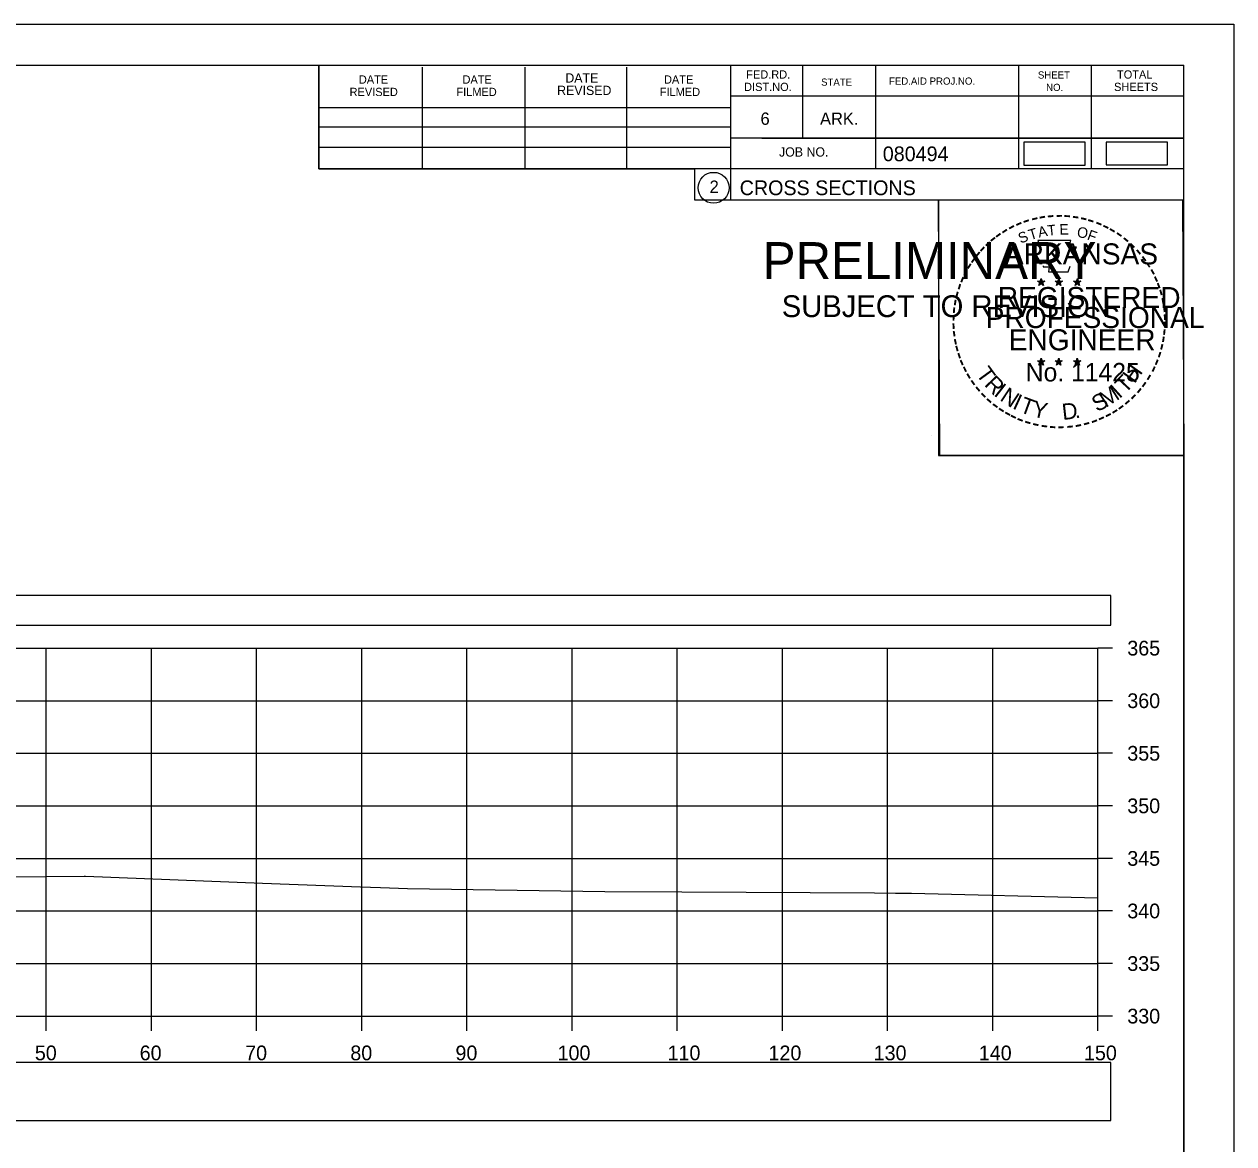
# Model space of a CAD drawing. Extents: x 1376273 to 1384221, y 378927 to 384592.
# Drawn here: x 1377105.7 to 1377220.7, y 380218.7 to 380325.2 of the extents above; entities that cross this region are included whole.
import ezdxf

# ---------------------------------------------------------------- set-up
doc = ezdxf.new("R2010")
doc.units = 0
for name, color, linetype in [('R_Axis', 7, 'Continuous'), ('R_Axis Annot', 7, 'Continuous'), ('R_Border', 7, 'Continuous'), ('R_Border PE', 7, 'Continuous'), ('R_Border Prem', 7, 'Continuous'), ('R_Drive', 7, 'Continuous'), ('R_Exist Surface', 7, 'Continuous'), ('R_Grid', 7, 'Continuous'), ('R_No Plot', 7, 'Continuous')]:
    doc.layers.add(name, color=color, linetype=linetype)

msp = doc.modelspace()

# ---------------------------------------------------------------- linework, layer by layer
at = {"layer": 'R_Axis'}
for p, q in [((1377207.77, 380230.82), (1377207.77, 380265.82)), ((1377209.17, 380265.82), (1377207.77, 380265.82)), ((1377209.17, 380260.82), (1377207.77, 380260.82)), ((1377209.17, 380255.82), (1377207.77, 380255.82)), ((1377209.17, 380250.82), (1377207.77, 380250.82)), ((1377209.17, 380245.82), (1377207.77, 380245.82)), ((1377209.17, 380240.82), (1377207.77, 380240.82)), ((1377209.17, 380235.82), (1377207.77, 380235.82)), ((1376907.77, 380230.82), (1377207.77, 380230.82)), ((1377107.77, 380229.42), (1377107.77, 380230.82)), ((1377117.77, 380229.42), (1377117.77, 380230.82)), ((1377127.77, 380229.42), (1377127.77, 380230.82)), ((1377137.77, 380229.42), (1377137.77, 380230.82)), ((1377147.77, 380229.42), (1377147.77, 380230.82)), ((1377157.77, 380229.42), (1377157.77, 380230.82)), ((1377167.77, 380229.42), (1377167.77, 380230.82)), ((1377177.77, 380229.42), (1377177.77, 380230.82)), ((1377187.77, 380229.42), (1377187.77, 380230.82)), ((1377197.77, 380229.42), (1377197.77, 380230.82)), ((1377207.77, 380229.42), (1377207.77, 380230.82)), ((1377209.17, 380230.82), (1377207.77, 380230.82))]:
    msp.add_line(p, q, dxfattribs=at)
at = {"layer": 'R_Axis Annot'}
for points in [[(1376907.2, 380268.02), (1377209.01, 380268.02), (1377209.01, 380270.84), (1376907.2, 380270.84)], [(1376907.2, 380220.89), (1377209.01, 380220.89), (1377209.01, 380226.41), (1376907.2, 380226.41)]]:
    msp.add_lwpolyline(points, close=True, dxfattribs=at)
at = {"layer": 'R_Border'}
for p, q in [((1376899.77, 380321.28), (1377215.95, 380321.28)), ((1377133.69, 380311.4), (1377133.69, 380321.28)), ((1377143.55, 380311.4), (1377143.55, 380321.08)), ((1377153.31, 380311.4), (1377153.31, 380321.08)), ((1377162.99, 380311.4), (1377162.99, 380321.08)), ((1377172.85, 380321.28), (1377172.85, 380308.48)), ((1377179.69, 380321.28), (1377179.69, 380314.34)), ((1377186.63, 380321.28), (1377186.63, 380311.4)), ((1377200.21, 380321.28), (1377200.21, 380311.4)), ((1377207.15, 380321.28), (1377207.15, 380311.4)), ((1377215.95, 380115.82), (1377215.95, 380321.28)), ((1377215.95, 380318.34), (1377172.85, 380318.34)), ((1377215.95, 380318.36), (1377215.95, 380318.36)), ((1377133.69, 380317.26), (1377172.85, 380317.26)), ((1377133.69, 380315.4), (1377172.85, 380315.4)), ((1377215.95, 380314.34), (1377172.85, 380314.34)), ((1377175.81, 380314.34), (1377215.95, 380314.34)), ((1377133.69, 380311.4), (1377133.69, 380313.46)), ((1377133.69, 380313.46), (1377172.85, 380313.46)), ((1377215.95, 380311.4), (1377133.69, 380311.4)), ((1377172.85, 380308.48), (1377215.95, 380308.48))]:
    msp.add_line(p, q, dxfattribs=at)
msp.add_circle((1377171.23, 380309.61), 1.47, dxfattribs=at)
at = {"layer": 'R_Border PE'}
for p, q in [((1377202.03, 380300.73), (1377202.38, 380300.62)), ((1377202.03, 380300.73), (1377202.29, 380300.69)), ((1377202.03, 380300.73), (1377202.27, 380300.61)), ((1377202.17, 380300.33), (1377202.38, 380300.62)), ((1377202.17, 380300.33), (1377202.29, 380300.57)), ((1377202.17, 380300.33), (1377202.38, 380300.54)), ((1377202.38, 380300.99), (1377202.34, 380300.74)), ((1377202.38, 380300.62), (1377202.38, 380300.99)), ((1377202.38, 380300.99), (1377202.43, 380300.74)), ((1377202.73, 380300.73), (1377202.38, 380300.62)), ((1377202.59, 380300.33), (1377202.38, 380300.62)), ((1377202.59, 380300.33), (1377202.38, 380300.54)), ((1377202.73, 380300.73), (1377202.44, 380300.68)), ((1377202.59, 380300.33), (1377202.46, 380300.62)), ((1377202.73, 380300.73), (1377202.52, 380300.63)), ((1377203.7, 380300.73), (1377204.05, 380300.62)), ((1377203.7, 380300.73), (1377203.96, 380300.69)), ((1377203.7, 380300.73), (1377203.94, 380300.61)), ((1377203.84, 380300.33), (1377204.05, 380300.62)), ((1377203.84, 380300.33), (1377203.96, 380300.57)), ((1377203.84, 380300.33), (1377204.05, 380300.54)), ((1377204.05, 380300.99), (1377204.01, 380300.74)), ((1377204.05, 380300.62), (1377204.05, 380300.99)), ((1377204.05, 380300.99), (1377204.1, 380300.74)), ((1377204.4, 380300.73), (1377204.05, 380300.62)), ((1377204.26, 380300.33), (1377204.05, 380300.62)), ((1377204.26, 380300.33), (1377204.05, 380300.54)), ((1377204.4, 380300.73), (1377204.11, 380300.68)), ((1377204.26, 380300.33), (1377204.13, 380300.62)), ((1377204.4, 380300.73), (1377204.19, 380300.63)), ((1377205.47, 380300.72), (1377205.82, 380300.61)), ((1377205.47, 380300.72), (1377205.72, 380300.68)), ((1377205.47, 380300.72), (1377205.7, 380300.6)), ((1377205.6, 380300.31), (1377205.82, 380300.61)), ((1377205.6, 380300.31), (1377205.73, 380300.56)), ((1377205.6, 380300.31), (1377205.81, 380300.53)), ((1377205.82, 380300.98), (1377205.77, 380300.72)), ((1377206.03, 380300.31), (1377205.81, 380300.53)), ((1377205.82, 380300.61), (1377205.82, 380300.98)), ((1377205.82, 380300.98), (1377205.86, 380300.73)), ((1377206.16, 380300.72), (1377205.82, 380300.61)), ((1377206.03, 380300.31), (1377205.82, 380300.61)), ((1377206.16, 380300.72), (1377205.88, 380300.67)), ((1377206.03, 380300.31), (1377205.89, 380300.6)), ((1377206.16, 380300.72), (1377205.96, 380300.62)), ((1377202.03, 380293.16), (1377202.38, 380293.05)), ((1377202.03, 380293.16), (1377202.28, 380293.12)), ((1377202.03, 380293.16), (1377202.27, 380293.04)), ((1377202.16, 380292.75), (1377202.38, 380293.05)), ((1377202.38, 380293.41), (1377202.34, 380293.16)), ((1377202.38, 380293.05), (1377202.38, 380293.41)), ((1377202.38, 380293.41), (1377202.43, 380293.16)), ((1377202.72, 380293.16), (1377202.38, 380293.05)), ((1377202.59, 380292.75), (1377202.38, 380293.05)), ((1377202.72, 380293.16), (1377202.44, 380293.11)), ((1377202.59, 380292.75), (1377202.45, 380293.04)), ((1377202.72, 380293.16), (1377202.52, 380293.06)), ((1377203.7, 380293.16), (1377204.05, 380293.05)), ((1377203.7, 380293.16), (1377203.95, 380293.12)), ((1377203.7, 380293.16), (1377203.93, 380293.04)), ((1377203.83, 380292.75), (1377204.05, 380293.05)), ((1377204.05, 380293.41), (1377204.01, 380293.16)), ((1377204.05, 380293.05), (1377204.05, 380293.41)), ((1377204.05, 380293.41), (1377204.1, 380293.16)), ((1377204.39, 380293.16), (1377204.05, 380293.05)), ((1377204.26, 380292.75), (1377204.05, 380293.05)), ((1377204.39, 380293.16), (1377204.11, 380293.11)), ((1377204.26, 380292.75), (1377204.12, 380293.04)), ((1377204.39, 380293.16), (1377204.19, 380293.06)), ((1377205.46, 380293.15), (1377205.81, 380293.04)), ((1377205.46, 380293.15), (1377205.72, 380293.11)), ((1377205.46, 380293.15), (1377205.7, 380293.03)), ((1377205.6, 380292.74), (1377205.81, 380293.04)), ((1377205.81, 380293.4), (1377205.77, 380293.15)), ((1377205.81, 380293.04), (1377205.81, 380293.4)), ((1377205.81, 380293.4), (1377205.86, 380293.15)), ((1377206.16, 380293.15), (1377205.81, 380293.04)), ((1377206.03, 380292.74), (1377205.81, 380293.04)), ((1377206.16, 380293.15), (1377205.87, 380293.1)), ((1377206.03, 380292.74), (1377205.89, 380293.03)), ((1377206.16, 380293.15), (1377205.96, 380293.05)), ((1377202.16, 380292.75), (1377202.29, 380293)), ((1377202.16, 380292.75), (1377202.38, 380292.97)), ((1377202.59, 380292.75), (1377202.38, 380292.97)), ((1377203.83, 380292.75), (1377203.96, 380293)), ((1377203.83, 380292.75), (1377204.04, 380292.97)), ((1377204.26, 380292.75), (1377204.04, 380292.97)), ((1377205.6, 380292.74), (1377205.72, 380292.99)), ((1377205.6, 380292.74), (1377205.81, 380292.96)), ((1377206.03, 380292.74), (1377205.81, 380292.96))]:
    msp.add_line(p, q, dxfattribs=at)
for points in [[(1377202.07, 380304.61), (1377202.34, 380303.78)], [(1377205.58, 380303.69), (1377205.73, 380303.97), (1377205.04, 380303.95), (1377205.19, 380304.61), (1377202.07, 380304.61)], [(1377202.57, 380302.19), (1377202.57, 380302.1), (1377203.13, 380302.08), (1377203.07, 380301.61), (1377204.94, 380301.61), (1377205.15, 380302.15)], [(1377202.38, 380300.99), (1377202.59, 380300.33), (1377202.03, 380300.73), (1377202.73, 380300.73), (1377202.17, 380300.33), (1377202.38, 380300.99)], [(1377204.05, 380300.99), (1377204.26, 380300.33), (1377203.7, 380300.73), (1377204.4, 380300.73), (1377203.84, 380300.33), (1377204.05, 380300.99)], [(1377205.82, 380300.98), (1377206.03, 380300.31), (1377205.47, 380300.72), (1377206.16, 380300.72), (1377205.6, 380300.31), (1377205.82, 380300.98)], [(1377202.38, 380293.41), (1377202.59, 380292.75), (1377202.03, 380293.16), (1377202.72, 380293.16), (1377202.16, 380292.75), (1377202.38, 380293.41)], [(1377204.05, 380293.41), (1377204.26, 380292.75), (1377203.7, 380293.16), (1377204.39, 380293.16), (1377203.83, 380292.75), (1377204.05, 380293.41)], [(1377205.81, 380293.4), (1377206.03, 380292.74), (1377205.46, 380293.15), (1377206.16, 380293.15), (1377205.6, 380292.74), (1377205.81, 380293.4)]]:
    msp.add_lwpolyline(points, dxfattribs=at)
for centre, radius in [((1377202.38, 380300.62), 0.172), ((1377202.38, 380300.62), 0.145), ((1377202.38, 380300.62), 0.116), ((1377202.38, 380300.62), 0.0991), ((1377202.38, 380300.62), 0.0747), ((1377202.38, 380300.62), 0.0495), ((1377202.38, 380300.62), 0.0296), ((1377204.05, 380300.62), 0.172), ((1377204.05, 380300.62), 0.145), ((1377204.05, 380300.62), 0.116), ((1377204.05, 380300.62), 0.0991), ((1377204.05, 380300.62), 0.0747), ((1377204.05, 380300.62), 0.0495), ((1377204.05, 380300.62), 0.0296), ((1377205.81, 380300.61), 0.172), ((1377205.81, 380300.61), 0.145), ((1377205.81, 380300.61), 0.116), ((1377205.81, 380300.61), 0.0991), ((1377205.81, 380300.61), 0.0747), ((1377205.81, 380300.61), 0.0495), ((1377205.81, 380300.61), 0.0296), ((1377202.38, 380293.05), 0.172), ((1377202.38, 380293.05), 0.145), ((1377202.38, 380293.05), 0.116), ((1377202.38, 380293.05), 0.0991), ((1377202.38, 380293.05), 0.0747), ((1377202.38, 380293.05), 0.0495), ((1377202.38, 380293.05), 0.0296), ((1377204.05, 380293.05), 0.172), ((1377204.05, 380293.05), 0.145), ((1377204.05, 380293.05), 0.116), ((1377204.05, 380293.05), 0.0991), ((1377204.05, 380293.05), 0.0747), ((1377204.05, 380293.05), 0.0495), ((1377204.05, 380293.05), 0.0296), ((1377205.81, 380293.04), 0.172), ((1377205.81, 380293.04), 0.145), ((1377205.81, 380293.04), 0.116), ((1377205.81, 380293.04), 0.0991), ((1377205.81, 380293.04), 0.0747), ((1377205.81, 380293.04), 0.0495), ((1377205.81, 380293.04), 0.0296)]:
    msp.add_circle(centre, radius, dxfattribs=at)
at = {"layer": 'R_Drive'}
for points in [[(1377200.72, 380311.77), (1377206.55, 380311.77), (1377206.55, 380313.96), (1377200.72, 380313.96)], [(1377208.55, 380311.78), (1377214.39, 380311.78), (1377214.39, 380313.96), (1377208.55, 380313.96)]]:
    msp.add_lwpolyline(points, close=True, dxfattribs=at)
at = {"layer": 'R_Exist Surface'}
msp.add_lwpolyline([(1377093.38, 380243.97), (1377111.36, 380244.14), (1377111.49, 380244.14), (1377128.33, 380243.45), (1377137.64, 380243.11), (1377139.54, 380243.04), (1377142.11, 380242.96), (1377160.87, 380242.67), (1377168.2, 380242.63), (1377186.53, 380242.54), (1377188.53, 380242.52), (1377190.06, 380242.52), (1377207.77, 380242.08)], dxfattribs=at)
at = {"layer": 'R_Grid'}
for p, q in [((1376907.77, 380265.82), (1377207.77, 380265.82)), ((1376907.77, 380265.82), (1377207.77, 380265.82)), ((1377107.77, 380230.82), (1377107.77, 380265.82)), ((1377107.77, 380230.82), (1377107.77, 380265.82)), ((1377117.77, 380230.82), (1377117.77, 380265.82)), ((1377117.77, 380230.82), (1377117.77, 380265.82)), ((1377127.77, 380230.82), (1377127.77, 380265.82)), ((1377127.77, 380230.82), (1377127.77, 380265.82)), ((1377137.77, 380230.82), (1377137.77, 380265.82)), ((1377137.77, 380230.82), (1377137.77, 380265.82)), ((1377147.77, 380230.82), (1377147.77, 380265.82)), ((1377147.77, 380230.82), (1377147.77, 380265.82)), ((1377157.77, 380230.82), (1377157.77, 380265.82)), ((1377157.77, 380230.82), (1377157.77, 380265.82)), ((1377167.77, 380230.82), (1377167.77, 380265.82)), ((1377167.77, 380230.82), (1377167.77, 380265.82)), ((1377177.77, 380230.82), (1377177.77, 380265.82)), ((1377177.77, 380230.82), (1377177.77, 380265.82)), ((1377187.77, 380230.82), (1377187.77, 380265.82)), ((1377187.77, 380230.82), (1377187.77, 380265.82)), ((1377197.77, 380230.82), (1377197.77, 380265.82)), ((1377197.77, 380230.82), (1377197.77, 380265.82)), ((1377207.77, 380230.82), (1377207.77, 380265.82)), ((1377207.77, 380230.82), (1377207.77, 380265.82)), ((1376907.77, 380260.82), (1377207.77, 380260.82)), ((1376907.77, 380260.82), (1377207.77, 380260.82)), ((1376907.77, 380255.82), (1377207.77, 380255.82)), ((1376907.77, 380255.82), (1377207.77, 380255.82)), ((1376907.77, 380250.82), (1377207.77, 380250.82)), ((1376907.77, 380250.82), (1377207.77, 380250.82)), ((1376907.77, 380245.82), (1377207.77, 380245.82)), ((1376907.77, 380245.82), (1377207.77, 380245.82)), ((1376907.77, 380240.82), (1377207.77, 380240.82)), ((1376907.77, 380240.82), (1377207.77, 380240.82)), ((1376907.77, 380235.82), (1377207.77, 380235.82)), ((1376907.77, 380235.82), (1377207.77, 380235.82)), ((1376907.77, 380230.82), (1377207.77, 380230.82)), ((1376907.77, 380230.82), (1377207.77, 380230.82))]:
    msp.add_line(p, q, dxfattribs=at)
at = {"layer": 'R_No Plot'}
for p, q in [((1376887.37, 380325.17), (1377220.7, 380325.17)), ((1377191.98, 380286.02), (1377191.98, 380286.02))]:
    msp.add_line(p, q, dxfattribs=at)
for points in [[(1376887.36, 380325.17), (1377220.7, 380325.17), (1377220.7, 380111.84), (1376887.36, 380111.84)], [(1377133.69, 380321.28), (1377133.69, 380311.4), (1377169.42, 380311.4), (1377169.42, 380308.48), (1377192.62, 380308.48), (1377192.62, 380284.15), (1377215.95, 380284.15), (1377215.95, 380115.82), (1376899.77, 380115.82), (1376899.77, 380321.28)], [(1377192.62, 380308.48), (1377215.83, 380308.48), (1377215.95, 380284.15), (1377192.74, 380284.15)]]:
    msp.add_lwpolyline(points, close=True, dxfattribs=at)

# ---------------------------------------------------------------- texts
at = {"layer": 'R_Axis Annot'}
for s, p in [('365', (1377210.57, 380265.12)), ('360', (1377210.57, 380260.12)), ('355', (1377210.57, 380255.12)), ('350', (1377210.57, 380250.12)), ('345', (1377210.57, 380245.12)), ('340', (1377210.57, 380240.12)), ('335', (1377210.57, 380235.12)), ('330', (1377210.57, 380230.12)), ('50', (1377106.68, 380226.62)), ('60', (1377116.65, 380226.62)), ('70', (1377126.68, 380226.62)), ('80', (1377136.68, 380226.62)), ('90', (1377146.68, 380226.62)), ('100', (1377156.39, 380226.62)), ('110', (1377166.85, 380226.62)), ('120', (1377176.45, 380226.62)), ('130', (1377186.45, 380226.62)), ('140', (1377196.45, 380226.62)), ('150', (1377206.45, 380226.62))]:
    msp.add_text(s, height=1.4, dxfattribs=at).set_placement(p)
at = {"layer": 'R_Border'}
for s, height, p in [('FED.RD.', 0.782, (1377174.33, 380320)), ('SHEET', 0.684, (1377202.07, 380320)), ('TOTAL', 0.782, (1377209.59, 380320)), ('DATE', 0.782, (1377137.49, 380319.52)), ('DATE', 0.782, (1377147.35, 380319.52)), ('DATE', 0.879, (1377157.13, 380319.62)), ('DATE', 0.782, (1377166.51, 380319.52)), ('DIST.NO.', 0.782, (1377174.13, 380318.82)), ('STATE', 0.684, (1377181.45, 380319.32)), ('FED.AID PROJ.NO.', 0.684, (1377187.91, 380319.42)), ('NO.', 0.684, (1377202.85, 380318.82)), ('SHEETS', 0.782, (1377209.31, 380318.82)), ('REVISED', 0.782, (1377136.61, 380318.34)), ('FILMED', 0.782, (1377146.77, 380318.34)), ('REVISED', 0.879, (1377156.35, 380318.44)), ('FILMED', 0.782, (1377166.11, 380318.34)), ('6', 1.17, (1377175.69, 380315.6)), ('ARK.', 1.172, (1377181.35, 380315.6)), ('JOB NO.', 0.879, (1377177.45, 380312.58)), ('080494', 1.4, (1377187.32, 380312.14)), ('2', 1.17, (1377170.85, 380309.13)), ('CROSS SECTIONS', 1.4, (1377173.71, 380308.91))]:
    msp.add_text(s, height=height, rotation=360, dxfattribs=at).set_placement(p)
at = {"layer": 'R_Border PE'}
for s, height, rotation, p in [('-', 1.6, 10.2193, (1377202.25, 380306.14)), ('-', 1.6, 5.8968, (1377202.98, 380306.25)), ('-', 1.6, 0.1862, (1377203.75, 380306.32)), ('-', 1.6, 357.743, (1377204.47, 380306.31)), ('-', 1.6, 352.1617, (1377205.22, 380306.25)), ('-', 1.6, 34.0636, (1377198.96, 380304.78)), ('-', 1.6, 28.7918, (1377199.55, 380305.15)), ('-', 1.6, 24.3072, (1377200.19, 380305.47)), ('-', 1.6, 19.1761, (1377200.82, 380305.74)), ('T', 1, 16.4036, (1377201.34, 380304.62)), ('-', 1.6, 13.6301, (1377201.57, 380305.98)), ('A', 1, 11.2132, (1377202.17, 380304.87)), ('T', 1, 6.0228, (1377203.02, 380305.04)), ('E', 1, 0.8323, (1377204.12, 380305.15)), ('O', 1, 350.4515, (1377205.73, 380304.94)), ('-', 1.6, 347.2049, (1377205.94, 380306.14)), ('-', 1.6, 342.3362, (1377206.57, 380305.99)), ('-', 1.6, 337.8551, (1377207.31, 380305.76)), ('-', 1.6, 334.1211, (1377207.94, 380305.49)), ('-', 1.6, 329.6409, (1377208.52, 380305.21)), ('-', 1.6, 42.9622, (1377197.47, 380303.59)), ('-', 1.6, 38.9507, (1377197.9, 380304.01)), ('-', 1.6, 36.2317, (1377198.38, 380304.39)), ('S', 1, 21.594, (1377200.43, 380304.29)), ('F', 1, 340.0707, (1377206.68, 380304.71)), ('-', 1.6, 325.8627, (1377209.16, 380304.85)), ('-', 1.6, 320.5297, (1377209.77, 380304.42)), ('-', 1.6, 50.6142, (1377196.62, 380302.63)), ('-', 1.6, 48.423, (1377197.02, 380303.11)), ('ARKANSAS', 2, 360, (1377198.93, 380302.32)), ('-', 1.6, 315.5786, (1377210.37, 380303.93)), ('-', 1.6, 309.8797, (1377210.94, 380303.38)), ('-', 1.6, 58.0706, (1377195.88, 380301.53)), ('-', 1.6, 54.2325, (1377196.21, 380302.06)), ('-', 1.6, 306.6522, (1377211.46, 380302.78)), ('-', 1.4, 303.6753, (1377211.95, 380302.21)), ('-', 1.6, 67.7743, (1377195.31, 380300.31)), ('-', 1.6, 62.8713, (1377195.57, 380300.92)), ('-', 1.6, 299.6684, (1377212.27, 380301.61)), ('-', 1.6, 294.6628, (1377212.59, 380300.99)), ('-', 1.6, 72.3945, (1377195.09, 380299.68)), ('REGISTERED', 2, 360, (1377198.25, 380298.17)), ('DWB', 0.01, 360, (1377202.37, 380300.62)), ('DWB', 0.01, 360, (1377204.04, 380300.62)), ('DWB', 0.01, 360, (1377205.8, 380300.61)), ('-', 1.6, 290.5728, (1377212.85, 380300.42)), ('-', 1.6, 285.1233, (1377213.08, 380299.84)), ('-', 1.6, 81.2013, (1377194.76, 380298.25)), ('-', 1.6, 75.461, (1377194.89, 380298.97)), ('-', 1.6, 280.5493, (1377213.28, 380299.1)), ('-', 1.6, 85.1863, (1377194.68, 380297.56)), ('PROFESSIONAL', 2, 360, (1377197.1, 380296.27)), ('-', 1.6, 276.5962, (1377213.44, 380298.33)), ('-', 1.6, 94.1959, (1377194.69, 380296.14)), ('-', 1.6, 89.0622, (1377194.66, 380296.86)), ('-', 1.6, 274.3301, (1377213.5, 380297.61)), ('-', 1.6, 269.9407, (1377213.54, 380296.97)), ('-', 1.6, 98.9479, (1377194.77, 380295.47)), ('ENGINEER', 2, 360, (1377199.29, 380294.15)), ('-', 1.6, 260.9953, (1377213.45, 380295.65)), ('-', 1.6, 263.5172, (1377213.52, 380296.31)), ('-', 1.6, 101.7149, (1377194.9, 380294.74)), ('-', 1.6, 105.4578, (1377195.06, 380294.14)), ('-', 1.6, 255.7626, (1377213.34, 380294.98)), ('-', 1.6, 109.0874, (1377195.28, 380293.51)), ('-', 1.6, 114.0643, (1377195.53, 380292.91)), ('DWB', 0.01, 360, (1377202.36, 380293.04)), ('DWB', 0.01, 360, (1377204.03, 380293.04)), ('DWB', 0.01, 360, (1377205.8, 380293.03)), ('-', 1.6, 247.8887, (1377212.93, 380293.58)), ('-', 1.6, 252.8681, (1377213.16, 380294.26)), ('-', 1.6, 115.7289, (1377195.84, 380292.3)), ('-', 1.6, 120.4471, (1377196.19, 380291.71)), ('T', 1.54, 306.0406, (1377196.14, 380291.89)), ('No. 11425', 1.757, 360, (1377200.91, 380291.19)), ('T', 1.54, 46.6444, (1377210.37, 380289.98)), ('H', 1.54, 54.6088, (1377211.26, 380290.92)), ('-', 1.6, 244.6197, (1377212.67, 380292.95)), ('-', 1.6, 125.8934, (1377196.6, 380291.15)), ('R', 1.54, 314.005, (1377196.9, 380290.84)), ('I', 1.54, 321.9694, (1377197.8, 380289.91)), ('M', 1.54, 32.6563, (1377208.52, 380288.66)), ('I', 1.54, 42.1136, (1377209.81, 380289.5)), ('-', 1.6, 233.8452, (1377211.88, 380291.55)), ('-', 1.6, 239.0712, (1377212.28, 380292.2)), ('-', 1.6, 130.7181, (1377197.06, 380290.6)), ('-', 1.6, 134.2238, (1377197.58, 380290.05)), ('-', 1.6, 138.9338, (1377198.1, 380289.59)), ('N', 1.54, 326.5002, (1377198.37, 380289.44)), ('I', 1.54, 335.3603, (1377199.57, 380288.65)), ('T', 1.54, 339.8912, (1377200.24, 380288.32)), ('S', 1.54, 26.9312, (1377207.68, 380288.25)), ('-', 1.6, 225.7653, (1377210.97, 380290.42)), ('-', 1.6, 231.2538, (1377211.45, 380290.98)), ('-', 1.6, 144.6463, (1377198.66, 380289.18)), ('-', 1.6, 148.0898, (1377199.22, 380288.81)), ('Y', 1.54, 347.8556, (1377201.45, 380287.88)), ('D', 1.54, 6.3969, (1377204.44, 380287.52)), ('-', 1.6, 212.2491, (1377209.36, 380289.05)), ('-', 1.6, 215.7363, (1377209.9, 380289.44)), ('-', 1.6, 221.0851, (1377210.44, 380289.91)), ('-', 1.6, 151.5704, (1377199.8, 380288.49)), ('-', 1.6, 154.6002, (1377200.32, 380288.24)), ('-', 1.6, 158.5612, (1377200.94, 380287.98)), ('-', 1.6, 162.7983, (1377201.63, 380287.77)), ('.', 1.54, 13.7642, (1377205.63, 380287.65)), ('-', 1.6, 195.4743, (1377206.88, 380287.87)), ('-', 1.6, 200.7184, (1377207.56, 380288.11)), ('-', 1.6, 204.2516, (1377208.18, 380288.39)), ('-', 1.6, 207.3568, (1377208.8, 380288.7)), ('-', 1.6, 167.5555, (1377202.35, 380287.61)), ('-', 1.6, 173.1155, (1377203.12, 380287.5)), ('-', 1.6, 176.5183, (1377203.87, 380287.44)), ('-', 1.6, 181.5918, (1377204.61, 380287.46)), ('-', 1.6, 185.8167, (1377205.42, 380287.54)), ('-', 1.6, 191.2858, (1377206.15, 380287.67))]:
    msp.add_text(s, height=height, rotation=rotation, dxfattribs=at).set_placement(p)
at = {"layer": 'R_Border Prem'}
for s, height, p in [('PRELIMINARY', 3.5, (1377175.9, 380300.94)), ('DWB', 0.01, (1377176.64, 380302.79)), ('SUBJECT TO REVISION', 2.0751, (1377177.71, 380297.31))]:
    msp.add_text(s, height=height, rotation=360, dxfattribs=at).set_placement(p)

doc.saveas('drawing.dxf')
